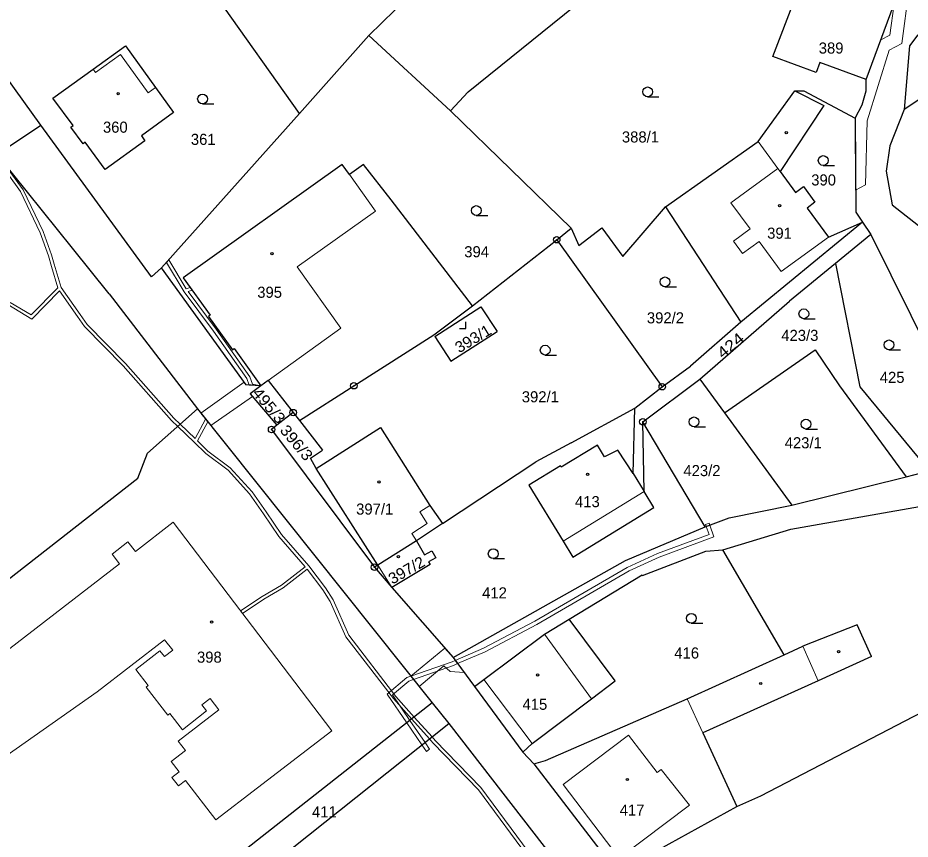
# Model space of a CAD drawing. Extents: x -727701 to -724405, y -960481 to -957284.
# Drawn here: x -726949 to -726812.2, y -958402.3 to -958276.3 of the extents above; entities that cross this region are included whole.
import ezdxf

# ---------------------------------------------------------------- set-up
doc = ezdxf.new("R2010")
doc.units = 0
doc.header["$LTSCALE"] = 0.68
for name, color, linetype, lineweight in [('1', 7, 'Continuous', 25), ('13', 7, 'Continuous', 13), ('3', 7, 'Continuous', 25), ('4', 7, 'Continuous', 13), ('5', 7, 'Continuous', 25), ('8', 7, 'Continuous', 25)]:
    doc.layers.add(name, color=color, linetype=linetype, lineweight=lineweight)
doc.layers.add('2', color=7, linetype='Continuous')

msp = doc.modelspace()

# ---------------------------------------------------------------- linework, layer by layer
at = {"layer": '1'}
for p, q in [((-726905.86, -958290.97), (-726926.62, -958261.65)), ((-726895.18, -958279.02), (-726882.45, -958266.5)), ((-726879.98, -958287.63), (-726857.92, -958269.86)), ((-726833.27, -958282.26), (-726828.66, -958270.21)), ((-726818.93, -958285.76), (-726814.24, -958272.97)), ((-726793.71, -958277.41), (-726813.11, -958290.35)), ((-726811.04, -958278.9), (-726812.28, -958280.58)), ((-726905.86, -958290.97), (-726895.18, -958279.02)), ((-726895.18, -958279.02), (-726882.7, -958290.55)), ((-726937.48, -958284.2), (-726932.53, -958280.62)), ((-726932.53, -958280.62), (-726927.9, -958287.01)), ((-726812.28, -958280.58), (-726813.11, -958290.35)), ((-726826.59, -958284.71), (-726833.27, -958282.26)), ((-726945.47, -958292.75), (-726952.38, -958283.24)), ((-726943.63, -958288.64), (-726937.48, -958284.2)), ((-726826.03, -958283.16), (-726826.59, -958284.71)), ((-726818.93, -958285.76), (-726826.03, -958283.16)), ((-726818.95, -958287.51), (-726818.93, -958285.76)), ((-726927.9, -958287.01), (-726925.13, -958290.84)), ((-726882.7, -958290.55), (-726879.98, -958287.63)), ((-726835.51, -958295.27), (-726829.88, -958287.51)), ((-726829.88, -958287.51), (-726828.49, -958287.51)), ((-726829.88, -958287.51), (-726825.46, -958289.76)), ((-726828.49, -958287.51), (-726820.64, -958291.68)), ((-726819.58, -958289.65), (-726818.95, -958287.51)), ((-726940.56, -958292.84), (-726943.63, -958288.64)), ((-726825.46, -958289.76), (-726832.13, -958299.87)), ((-726820.64, -958291.68), (-726819.58, -958289.65)), ((-726925.13, -958290.84), (-726930.08, -958294.42)), ((-726927, -958314.67), (-726905.86, -958290.97)), ((-726864.18, -958308.58), (-726882.7, -958290.55)), ((-726813.11, -958290.35), (-726815.32, -958295.94)), ((-726820.64, -958291.68), (-726820.53, -958306.1)), ((-726952.21, -958297.25), (-726945.47, -958292.75)), ((-726928.54, -958316.03), (-726945.47, -958292.75)), ((-726940.89, -958293.08), (-726940.56, -958292.84)), ((-726939.02, -958295.64), (-726940.89, -958293.08)), ((-726938.69, -958295.4), (-726939.02, -958295.64)), ((-726935.65, -958299.57), (-726938.69, -958295.4)), ((-726929.55, -958295.15), (-726935.65, -958299.57)), ((-726930.08, -958294.42), (-726929.55, -958295.15)), ((-726849.7, -958305.3), (-726835.51, -958295.27)), ((-726815.32, -958295.94), (-726815.88, -958299.81)), ((-726940.64, -958311.65), (-726952.21, -958297.25)), ((-726899.27, -958298.81), (-726923.68, -958316.17)), ((-726898.17, -958300.35), (-726899.27, -958298.81)), ((-726896.01, -958298.81), (-726898.17, -958300.35)), ((-726891.78, -958304.24), (-726896.01, -958298.81)), ((-726832.13, -958299.87), (-726829.78, -958303.07)), ((-726815.88, -958299.81), (-726814.98, -958304.97)), ((-726829.78, -958303.07), (-726828.57, -958302.19)), ((-726828.57, -958302.19), (-726826.81, -958304.59)), ((-726879.32, -958320.48), (-726891.78, -958304.24)), ((-726826.81, -958304.59), (-726828.01, -958305.48)), ((-726814.98, -958304.97), (-726810.21, -958308.73)), ((-726856.25, -958312.9), (-726849.7, -958305.3)), ((-726849.7, -958305.3), (-726838.17, -958322.98)), ((-726828.01, -958305.48), (-726824.74, -958309.93)), ((-726820.53, -958306.1), (-726819.51, -958307.64)), ((-726819.51, -958307.64), (-726838.17, -958322.98)), ((-726824.74, -958309.93), (-726819.51, -958307.64)), ((-726819.51, -958307.64), (-726818.24, -958309.55)), ((-726866.4, -958310.33), (-726864.18, -958308.58)), ((-726864.18, -958308.58), (-726863, -958311.24)), ((-726863, -958311.24), (-726859.5, -958308.5)), ((-726859.5, -958308.5), (-726856.25, -958312.9)), ((-726879.32, -958320.48), (-726866.4, -958310.33)), ((-726866.4, -958310.33), (-726850.21, -958332.88)), ((-726818.24, -958309.55), (-726823.65, -958313.99)), ((-726818.24, -958309.55), (-726802.3, -958341.7)), ((-726935.02, -958318.62), (-726940.64, -958311.65)), ((-726823.65, -958313.99), (-726830.68, -958319.76)), ((-726823.65, -958313.99), (-726819.9, -958332.9)), ((-726927, -958314.67), (-726928.54, -958316.03)), ((-726914, -958332.59), (-726927, -958314.67)), ((-726923.68, -958316.17), (-726919.55, -958321.92)), ((-726935.02, -958318.62), (-726921.49, -958336.29)), ((-726844.45, -958331.71), (-726830.68, -958319.76)), ((-726885.23, -958324.92), (-726879.32, -958320.48)), ((-726885.06, -958325.18), (-726878.01, -958320.62)), ((-726878.01, -958320.62), (-726875.55, -958324.39)), ((-726919.55, -958321.92), (-726919.79, -958322.09)), ((-726919.79, -958322.09), (-726916.12, -958327.21)), ((-726838.17, -958322.98), (-726845.89, -958329.74)), ((-726897.49, -958332.73), (-726885.23, -958324.92)), ((-726885.06, -958325.18), (-726882.62, -958328.96)), ((-726882.62, -958328.96), (-726875.55, -958324.39)), ((-726916.12, -958327.21), (-726915.87, -958327.03)), ((-726915.87, -958327.03), (-726911.77, -958332.74)), ((-726850.21, -958332.88), (-726845.89, -958329.74)), ((-726910.64, -958331.92), (-726911.77, -958332.74)), ((-726910.64, -958331.92), (-726906.8, -958336.85)), ((-726853.2, -958338.27), (-726844.45, -958331.71)), ((-726844.45, -958331.71), (-726840.68, -958336.87)), ((-726911.77, -958332.74), (-726914, -958332.59)), ((-726911.77, -958332.74), (-726913.38, -958333.99)), ((-726905.85, -958338.06), (-726897.49, -958332.73)), ((-726854.44, -958336.17), (-726850.21, -958332.88)), ((-726819.9, -958332.9), (-726809.31, -958345.8)), ((-726913.38, -958333.99), (-726909.3, -958338.8)), ((-726929.13, -958343.09), (-726921.49, -958336.29)), ((-726921.49, -958336.29), (-726885.47, -958381.37)), ((-726864.2, -958341.5), (-726854.44, -958336.17)), ((-726854.66, -958346.21), (-726854.44, -958336.17)), ((-726906.8, -958336.85), (-726909.3, -958338.8)), ((-726906.8, -958336.85), (-726905.85, -958338.06)), ((-726840.68, -958336.87), (-726830.33, -958351.03)), ((-726909.3, -958338.8), (-726910.11, -958339.43)), ((-726905.85, -958338.06), (-726902.33, -958342.59)), ((-726903.28, -958345.42), (-726893.43, -958339.13)), ((-726893.43, -958339.13), (-726885.84, -958351.08)), ((-726852.98, -958348.96), (-726853.2, -958338.27)), ((-726843.62, -958354.35), (-726853.2, -958338.27)), ((-726910.11, -958339.43), (-726894.34, -958360.56)), ((-726864.2, -958341.5), (-726869.6, -958344.4)), ((-726860.16, -958341.85), (-726865.7, -958345.23)), ((-726859.06, -958343.65), (-726860.16, -958341.85)), ((-726930.6, -958346.92), (-726929.13, -958343.09)), ((-726904.14, -958343.82), (-726902.33, -958342.59)), ((-726857.04, -958342.6), (-726859.06, -958343.65)), ((-726854.66, -958346.21), (-726857.04, -958342.6)), ((-726903.28, -958345.42), (-726904.14, -958343.82)), ((-726883.89, -958353.88), (-726869.6, -958344.4)), ((-726893.83, -958360.24), (-726903.28, -958345.42)), ((-726865.84, -958344.99), (-726870.69, -958347.96)), ((-726865.7, -958345.23), (-726865.84, -958344.99)), ((-726812.83, -958346.68), (-726809.31, -958345.8)), ((-726967.67, -958375.82), (-726930.6, -958346.92)), ((-726854.66, -958346.21), (-726852.98, -958348.96)), ((-726830.33, -958351.03), (-726812.83, -958346.68)), ((-726870.69, -958347.96), (-726865.43, -958356.57)), ((-726851.48, -958351.41), (-726852.98, -958348.96)), ((-726885.84, -958351.08), (-726883.89, -958353.88)), ((-726863.93, -958359.02), (-726851.48, -958351.41)), ((-726839.96, -958353.01), (-726830.33, -958351.03)), ((-726830.51, -958354.75), (-726806.58, -958350.51)), ((-726883.89, -958353.88), (-726887.91, -958356.54)), ((-726843.62, -958354.35), (-726839.96, -958353.01)), ((-726855.84, -958359.52), (-726843.62, -958354.35)), ((-726840.95, -958357.9), (-726830.51, -958354.75)), ((-726887.91, -958356.54), (-726893.83, -958360.24)), ((-726887.91, -958356.54), (-726886.66, -958358.67)), ((-726865.43, -958356.57), (-726863.93, -958359.02)), ((-726886.66, -958358.67), (-726885.56, -958358.03)), ((-726885.56, -958358.03), (-726884.93, -958359.11)), ((-726853.23, -958361.82), (-726843.51, -958358.12)), ((-726843.51, -958358.12), (-726840.95, -958357.9)), ((-726831.54, -958373.99), (-726840.95, -958357.9)), ((-726884.93, -958359.11), (-726886.03, -958359.75)), ((-726882.27, -958374.43), (-726855.84, -958359.52)), ((-726893.83, -958360.24), (-726894.34, -958360.56)), ((-726894.34, -958360.56), (-726891.66, -958363.65)), ((-726885.81, -958360.13), (-726891.66, -958363.65)), ((-726886.03, -958359.75), (-726885.81, -958360.13)), ((-726864.51, -958368.52), (-726853.3, -958361.74)), ((-726853.3, -958361.74), (-726853.23, -958361.82)), ((-726891.66, -958363.65), (-726882.27, -958374.43)), ((-726868.29, -958370.82), (-726864.51, -958368.52)), ((-726857.42, -958378), (-726864.51, -958368.52)), ((-726820.32, -958369.39), (-726828.67, -958372.68)), ((-726818.14, -958374.28), (-726820.32, -958369.39)), ((-726877.59, -958377.79), (-726868.29, -958370.82)), ((-726835.12, -958395.65), (-726791.52, -958372.96)), ((-726831.54, -958373.99), (-726828.67, -958372.68)), ((-726882.27, -958374.43), (-726879.01, -958378.86)), ((-726846.37, -958380.77), (-726831.54, -958373.99)), ((-726818.14, -958374.28), (-726826.32, -958377.98)), ((-726879.01, -958378.86), (-726877.59, -958377.79)), ((-726879.01, -958378.86), (-726871.59, -958388.94)), ((-726861.04, -958380.74), (-726857.42, -958378)), ((-726826.32, -958377.98), (-726844.01, -958385.98)), ((-726885.47, -958381.37), (-726922.74, -958410.62)), ((-726885.47, -958381.37), (-726882.93, -958384.54)), ((-726870.16, -958387.62), (-726861.04, -958380.74)), ((-726868.13, -958390.21), (-726846.37, -958380.77)), ((-726919.69, -958413.75), (-726882.93, -958384.54)), ((-726882.93, -958384.54), (-726852.38, -958423.88)), ((-726844.01, -958385.98), (-726838.78, -958397.26)), ((-726871.59, -958388.94), (-726870.16, -958387.62)), ((-726871.59, -958388.94), (-726869.9, -958390.7)), ((-726869.9, -958390.7), (-726868.13, -958390.21)), ((-726869.9, -958390.7), (-726857, -958407.5)), ((-726838.78, -958397.26), (-726835.12, -958395.65)), ((-726855.71, -958406.56), (-726838.78, -958397.26))]:
    msp.add_line(p, q, dxfattribs=at)
msp.add_lwpolyline([(-726840.68, -958336.87), (-726826.78, -958327.23), (-726823.04, -958332.76), (-726812.83, -958346.68)], dxfattribs=at)
at = {"layer": '13'}
for points in [[(-726813.98, -958269.94), (-726814.24, -958272.97), (-726814.68, -958274.17), (-726815.32, -958278.95), (-726816.7, -958279.69), (-726818.93, -958285.76), (-726818.95, -958287.51), (-726819.58, -958289.65), (-726820.64, -958291.68), (-726820.56, -958302.76), (-726819.07, -958301.91), (-726818.8, -958292.08), (-726815.44, -958281.28), (-726813.48, -958280.23), (-726812.39, -958272.12)], [(-726926.24, -958313.82), (-726923.51, -958318.31), (-726919.01, -958324.35), (-726913.9, -958331.61), (-726913.57, -958332.62), (-726911.77, -958332.74), (-726913.04, -958332.49), (-726913.46, -958331.38), (-726918.61, -958324.06), (-726922.9, -958318.29), (-726922.3, -958318.09), (-726922.61, -958317.66), (-726923.2, -958317.86), (-726925.89, -958313.43)], [(-726920.97, -958336.94), (-726919.44, -958338.85), (-726913.06, -958334.37), (-726913.38, -958333.99), (-726911.77, -958332.74), (-726914, -958332.59), (-726914.3, -958332.18)], [(-726843.04, -958355.54), (-726850.94, -958358.44), (-726855.58, -958360.6), (-726869.77, -958368.82), (-726877.63, -958373), (-726881.96, -958374.85), (-726881.59, -958375.35), (-726877.37, -958373.54), (-726869.47, -958369.34), (-726855.3, -958361.14), (-726850.7, -958359), (-726842.28, -958355.9), (-726842.93, -958354.1), (-726843.49, -958354.3)], [(-726843.03, -958353.83), (-726843.59, -958354.03), (-726843.49, -958354.3), (-726842.93, -958354.1)], [(-726888.74, -958377.28), (-726887.49, -958378.84), (-726883.7, -958375.68), (-726882.74, -958376.58), (-726880.57, -958376.73), (-726882.27, -958374.43), (-726883.55, -958372.96)], [(-726881.59, -958375.35), (-726881.96, -958374.85), (-726882.45, -958375.06), (-726888.75, -958377.27), (-726888.34, -958377.77), (-726882.23, -958375.62)], [(-726888.9, -958384.07), (-726891.6, -958380.13), (-726889.07, -958378.03), (-726888.34, -958377.77), (-726888.75, -958377.27), (-726889.37, -958377.49), (-726892.4, -958380.01), (-726889.38, -958384.44), (-726887.06, -958387.82), (-726886.38, -958388.82), (-726885.88, -958388.48), (-726886.59, -958387.45)]]:
    msp.add_lwpolyline(points, close=True, dxfattribs=at)
for points in [[(-726952.3, -958297.89), (-726948.61, -958302.95), (-726945.62, -958309.28), (-726944.33, -958312.79), (-726943.85, -958314.44), (-726942.88, -958317.72), (-726946.96, -958321.87), (-726950.19, -958319.94)], [(-726869.76, -958405.52), (-726878.03, -958394.36), (-726885.02, -958387.14), (-726885.51, -958386.59), (-726888.23, -958383.54), (-726891.06, -958380.37), (-726898.28, -958370.97), (-726900.67, -958365.57), (-726901.87, -958363.74), (-726904.4, -958360.37), (-726908.59, -958355.53), (-726910.92, -958352.08), (-726913.1, -958349.02), (-726916.44, -958345.3), (-726919.87, -958342.74), (-726921.46, -958341.18), (-726919.9, -958338.27), (-726920.24, -958337.85), (-726921.84, -958340.82), (-726924.12, -958338.63), (-726925.09, -958337.69), (-726932.5, -958329.33), (-726938.41, -958323.33), (-726939.48, -958321.8), (-726942.37, -958317.68), (-726943.43, -958314.08), (-726943.86, -958312.63), (-726945.16, -958309.09), (-726948.18, -958302.69), (-726951.92, -958297.6)], [(-726950.58, -958320.29), (-726946.88, -958322.5), (-726942.63, -958318.18), (-726939.89, -958322.09), (-726938.79, -958323.65), (-726932.87, -958329.68), (-726925.45, -958338.04), (-726924.49, -958338.96), (-726921.97, -958341.39), (-726920.2, -958343.12), (-726916.78, -958345.68), (-726913.49, -958349.33), (-726911.33, -958352.37), (-726908.99, -958355.83), (-726904.95, -958360.49), (-726908.6, -958363.31), (-726911.58, -958365.03), (-726914.87, -958367.25), (-726914.57, -958367.65), (-726911.31, -958365.45), (-726908.32, -958363.72), (-726904.64, -958360.88), (-726902.28, -958364.03), (-726901.11, -958365.81), (-726898.72, -958371.23), (-726891.44, -958380.69), (-726888.63, -958383.85), (-726885.9, -958386.9), (-726885.38, -958387.48), (-726878.41, -958394.68), (-726870.15, -958405.83)]]:
    msp.add_lwpolyline(points, dxfattribs=at)
at = {"layer": '3'}
for p, q in [((-726852.463, -958288.41), (-726850.713, -958288.41)), ((-726920.703, -958289.49), (-726918.953, -958289.49)), ((-726825.533, -958298.94), (-726823.783, -958298.94)), ((-726878.733, -958306.61), (-726876.983, -958306.61)), ((-726849.793, -958317.55), (-726848.043, -958317.55)), ((-726828.503, -958322.45), (-726826.753, -958322.45)), ((-726868.163, -958328.02), (-726866.413, -958328.02)), ((-726815.453, -958327.21), (-726813.703, -958327.21)), ((-726845.343, -958339.02), (-726843.593, -958339.02)), ((-726828.183, -958339.37), (-726826.433, -958339.37)), ((-726876.133, -958359.25), (-726874.383, -958359.25)), ((-726845.763, -958369.15), (-726844.013, -958369.15))]:
    msp.add_line(p, q, dxfattribs=at)
msp.add_lwpolyline([(-726881.311, -958323.95), (-726880.31, -958323.95), (-726880.31, -958322.95)], dxfattribs=at)
for centre in [(-726852.4629, -958287.6598), (-726920.7029, -958288.7398), (-726825.5329, -958298.1898), (-726878.7329, -958305.8598), (-726849.7929, -958316.7998), (-726828.5029, -958321.6998), (-726868.1629, -958327.2698), (-726815.4529, -958326.4598), (-726845.3429, -958338.2698), (-726828.1829, -958338.6198), (-726876.1329, -958358.4998), (-726845.7629, -958368.3998)]:
    msp.add_circle(centre, 0.75, dxfattribs=at)
at = {"layer": '4'}
for p, q in [((-726937.1, -958284.71), (-726933.3, -958281.95)), ((-726933.3, -958281.95), (-726929.04, -958287.83)), ((-726937.48, -958284.2), (-726937.1, -958284.71)), ((-726929.04, -958287.83), (-726927.9, -958287.01)), ((-726832.48, -958299.39), (-726835.51, -958295.27)), ((-726839.69, -958304.69), (-726832.48, -958299.39)), ((-726832.48, -958299.39), (-726832.13, -958299.87)), ((-726898.17, -958300.35), (-726894.17, -958305.98)), ((-726836.76, -958308.68), (-726839.69, -958304.69)), ((-726894.17, -958305.98), (-726906.18, -958314.5)), ((-726839.31, -958310.56), (-726836.76, -958308.68)), ((-726824.74, -958309.93), (-726831.96, -958315.22)), ((-726837.91, -958312.46), (-726839.31, -958310.56)), ((-726835.36, -958310.59), (-726837.91, -958312.46)), ((-726831.96, -958315.22), (-726835.36, -958310.59)), ((-726906.18, -958314.5), (-726899.52, -958323.89)), ((-726899.52, -958323.89), (-726910.64, -958331.92)), ((-726852.98, -958348.96), (-726865.43, -958356.57)), ((-726885.84, -958351.08), (-726887.39, -958352.07)), ((-726887.39, -958352.07), (-726886.24, -958353.88)), ((-726931, -958358.16), (-726925.18, -958353.66)), ((-726925.18, -958353.66), (-726900.9, -958385.68)), ((-726886.24, -958353.88), (-726888.63, -958355.41)), ((-726888.63, -958355.41), (-726887.91, -958356.54)), ((-726934.56, -958358.56), (-726932.14, -958356.69)), ((-726932.14, -958356.69), (-726931, -958358.16)), ((-726933.42, -958360.03), (-726934.56, -958358.56)), ((-726961.58, -958381.78), (-726933.42, -958360.03)), ((-726891.66, -958363.65), (-726893.83, -958360.24)), ((-726926.52, -958371.68), (-726936.86, -958379.66)), ((-726925.27, -958373.29), (-726926.52, -958371.68)), ((-726868.29, -958370.82), (-726861.04, -958380.74)), ((-726930.93, -958376.25), (-726927.23, -958373.39)), ((-726927.23, -958373.39), (-726926.55, -958374.27)), ((-726926.55, -958374.27), (-726925.27, -958373.29)), ((-726826.32, -958377.98), (-726828.67, -958372.68)), ((-726929.03, -958378.71), (-726930.93, -958376.25)), ((-726929.35, -958378.95), (-726929.03, -958378.71)), ((-726870.16, -958387.62), (-726877.59, -958377.79)), ((-726936.86, -958379.66), (-726953.95, -958391.66)), ((-726926.02, -958383.26), (-726929.35, -958378.95)), ((-726919.53, -958380.7), (-726920.79, -958381.68)), ((-726918.2, -958382.43), (-726919.53, -958380.7)), ((-726846.37, -958380.77), (-726844.01, -958385.98)), ((-726924.45, -958387.22), (-726918.2, -958382.43)), ((-726920.08, -958382.61), (-726923.79, -958385.48)), ((-726920.79, -958381.68), (-726920.08, -958382.61)), ((-726925.7, -958383.01), (-726926.02, -958383.26)), ((-726923.79, -958385.48), (-726925.7, -958383.01)), ((-726900.9, -958385.68), (-726912.29, -958394.41)), ((-726865.4, -958393.89), (-726855.37, -958386.3)), ((-726855.37, -958386.3), (-726851, -958392.07)), ((-726923.33, -958388.67), (-726924.45, -958387.22)), ((-726925.52, -958390.34), (-726923.33, -958388.67)), ((-726924.29, -958391.95), (-726925.52, -958390.34)), ((-726925.39, -958392.79), (-726924.29, -958391.95)), ((-726851, -958392.07), (-726850.38, -958391.6)), ((-726850.38, -958391.6), (-726846.05, -958397.05)), ((-726924.39, -958394.1), (-726925.39, -958392.79)), ((-726923.29, -958393.25), (-726924.39, -958394.1)), ((-726918.66, -958399.29), (-726923.29, -958393.25)), ((-726856.84, -958405.19), (-726865.4, -958393.89)), ((-726912.29, -958394.41), (-726918.66, -958399.29)), ((-726846.05, -958397.05), (-726856.84, -958405.19))]:
    msp.add_line(p, q, dxfattribs=at)
at = {"layer": '5'}
for centre in [(-726933.6368, -958287.9492), (-726831.2068, -958293.8992), (-726832.2168, -958305.0992), (-726910.0568, -958312.4592), (-726893.6468, -958347.4892), (-726861.6568, -958346.3092), (-726890.6668, -958358.9392), (-726919.3168, -958368.9792), (-726823.1768, -958373.5292), (-726869.3368, -958377.0892), (-726835.1068, -958378.3992), (-726855.5468, -958393.1192)]:
    msp.add_circle(centre, 0.175, dxfattribs=at)
at = {"layer": '8'}
for centre, radius in [((-726866.4, -958310.3299), 0.5), ((-726866.4, -958310.3299), 0.0303), ((-726897.49, -958332.7299), 0.5), ((-726897.49, -958332.7299), 0.0303), ((-726850.21, -958332.8799), 0.5), ((-726850.21, -958332.8799), 0.0303), ((-726906.8, -958336.8499), 0.5), ((-726906.8, -958336.8499), 0.0303), ((-726853.2, -958338.2699), 0.5), ((-726910.11, -958339.4299), 0.5), ((-726853.2, -958338.2699), 0.0303), ((-726910.11, -958339.4299), 0.0303), ((-726894.34, -958360.5599), 0.5), ((-726894.34, -958360.5599), 0.0303)]:
    msp.add_circle(centre, radius, dxfattribs=at)

# ---------------------------------------------------------------- texts
at = {"layer": '2'}
for s, p in [('389', (-726826.22, -958281.785)), ('360', (-726935.97, -958293.925)), ('388/1', (-726856.4, -958295.425)), ('361', (-726922.49, -958295.795)), ('390', (-726827.37, -958302.015)), ('391', (-726834.13, -958310.185)), ('394', (-726880.57, -958313.025)), ('395', (-726912.31, -958319.245)), ('392/2', (-726852.57, -958323.165)), ('423/3', (-726831.96, -958325.855)), ('425', (-726816.86, -958332.295)), ('392/1', (-726871.75, -958335.275)), ('423/1', (-726831.44, -958342.325)), ('423/2', (-726846.97, -958346.595)), ('413', (-726863.59, -958351.355)), ('397/1', (-726897.15, -958352.495)), ('412', (-726877.83, -958365.345)), ('416', (-726848.36, -958374.565)), ('398', (-726921.55, -958375.205)), ('415', (-726871.64, -958382.435)), ('411', (-726903.92, -958398.935)), ('417', (-726856.74, -958398.665))]:
    msp.add_text(s, height=1.7, dxfattribs=at).set_placement(p)
for s, rotation, width, p in [('393/1', 31, 1.05, (-726881.351, -958327.784)), ('424', 40, 1.2, (-726840.946, -958328.665)), ('495/3', 310, 1.1, (-726913.165, -958333.913)), ('396/3', 310, 1.1, (-726908.955, -958339.623)), ('397/2', 30, 1.05, (-726891.587, -958363.248))]:
    msp.add_text(s, height=1.7, rotation=rotation, dxfattribs=dict(at, width=width)).set_placement(p)

doc.saveas('drawing.dxf')
